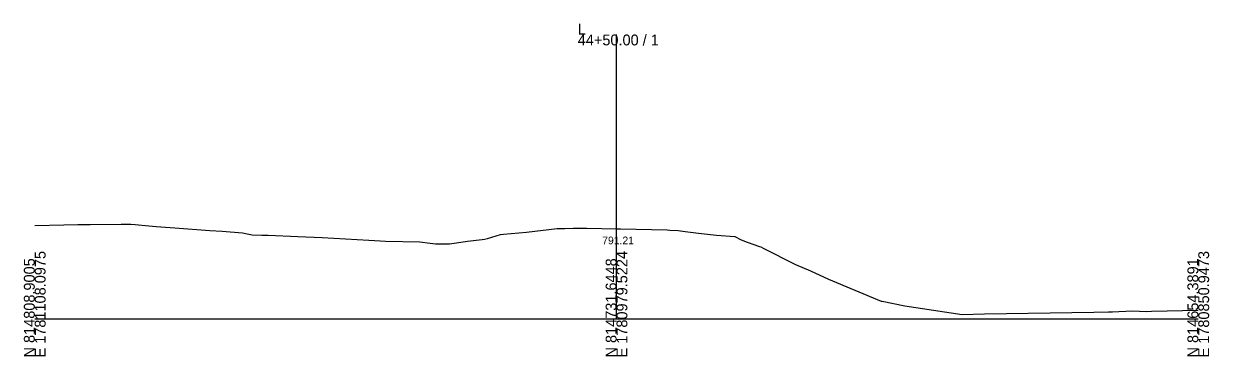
# Model space of a CAD drawing. Extents: x -26 to 7903, y -10 to 9573.
# Drawn here: x 997.2 to 1302.8, y 5490.3 to 5576.1 of the extents above; entities that cross this region are included whole.
import ezdxf

# ---------------------------------------------------------------- set-up
doc = ezdxf.new("R2010")
doc.units = 0
for name, color, linetype in [('Exist Cross Section Cell', 7, 'Continuous'), ('Exist XS Center Line Elevation Label', 7, 'Continuous'), ('Exist XS Ground Line', 7, 'Continuous')]:
    doc.layers.add(name, color=color, linetype=linetype)

msp = doc.modelspace()

# ---------------------------------------------------------------- linework, layer by layer
at = {"layer": 'Exist Cross Section Cell'}
for p, q in [((1150, 5500), (1150, 5573.35)), ((1000, 5500), (1150, 5500)), ((1150, 5500), (1300, 5500))]:
    msp.add_line(p, q, dxfattribs=at)
at = {"layer": 'Exist XS Ground Line'}
for p, q in [((1000, 5524.07), (1007.47, 5524.23)), ((1007.47, 5524.23), (1011.1, 5524.31)), ((1011.1, 5524.31), (1014.31, 5524.34)), ((1014.31, 5524.34), (1022.25, 5524.45)), ((1022.25, 5524.45), (1024.76, 5524.38)), ((1024.76, 5524.38), (1025.88, 5524.34)), ((1025.88, 5524.34), (1029.41, 5523.99)), ((1029.41, 5523.99), (1031.28, 5523.79)), ((1031.28, 5523.79), (1036.14, 5523.45)), ((1036.14, 5523.45), (1045.18, 5522.79)), ((1045.18, 5522.79), (1048.3, 5522.57)), ((1048.3, 5522.57), (1053.55, 5522.17)), ((1053.55, 5522.17), (1054.81, 5521.9)), ((1054.81, 5521.9), (1056.05, 5521.64)), ((1056.05, 5521.64), (1058.55, 5521.61)), ((1058.55, 5521.61), (1060.15, 5521.56)), ((1060.15, 5521.56), (1067.85, 5521.2)), ((1067.85, 5521.2), (1074.09, 5520.97)), ((1074.09, 5520.97), (1086.1, 5520.26)), ((1115.94, 5520.56), (1116.74, 5520.73)), ((1116.74, 5520.73), (1120.08, 5521.71)), ((1120.08, 5521.71), (1120.9, 5521.8)), ((1120.9, 5521.8), (1126.79, 5522.36)), ((1126.79, 5522.36), (1134.7, 5523.26)), ((1134.7, 5523.26), (1136.64, 5523.33)), ((1136.64, 5523.33), (1138.85, 5523.4)), ((1138.85, 5523.4), (1142.32, 5523.34)), ((1142.32, 5523.34), (1150, 5523.21)), ((1150, 5523.21), (1150.66, 5523.2)), ((1150.66, 5523.2), (1151, 5523.19)), ((1151, 5523.19), (1163.04, 5522.93)), ((1163.04, 5522.93), (1163.77, 5522.89)), ((1163.77, 5522.89), (1165.91, 5522.79)), ((1165.91, 5522.79), (1167.74, 5522.56)), ((1167.74, 5522.56), (1171.15, 5522.07)), ((1171.15, 5522.07), (1175.79, 5521.59)), ((1175.79, 5521.59), (1180.49, 5521.22)), ((1180.49, 5521.22), (1182.17, 5520.38)), ((1086.1, 5520.26), (1089.09, 5520.07)), ((1089.09, 5520.07), (1090.48, 5520.06)), ((1090.48, 5520.06), (1099.27, 5519.84)), ((1099.27, 5519.84), (1101.97, 5519.47)), ((1101.97, 5519.47), (1103.29, 5519.31)), ((1103.29, 5519.31), (1103.92, 5519.35)), ((1103.92, 5519.35), (1106.94, 5519.37)), ((1106.94, 5519.37), (1111.06, 5519.96)), ((1111.06, 5519.96), (1111.55, 5520.04)), ((1111.55, 5520.04), (1115.37, 5520.49)), ((1115.37, 5520.49), (1115.94, 5520.56)), ((1182.17, 5520.38), (1183.69, 5519.76)), ((1183.69, 5519.76), (1186.86, 5518.65)), ((1186.86, 5518.65), (1187.2, 5518.52)), ((1187.2, 5518.52), (1187.78, 5518.21)), ((1187.78, 5518.21), (1196.15, 5513.96)), ((1196.15, 5513.96), (1200.04, 5512.39)), ((1200.04, 5512.39), (1204.7, 5510.24)), ((1204.7, 5510.24), (1218.21, 5504.5)), ((1218.21, 5504.5), (1218.53, 5504.5)), ((1218.53, 5504.5), (1224.3, 5503.31)), ((1224.3, 5503.31), (1239.1, 5501.12)), ((1239.1, 5501.12), (1244.91, 5501.29)), ((1244.91, 5501.29), (1273.07, 5501.73)), ((1273.07, 5501.73), (1276.87, 5501.81)), ((1276.87, 5501.81), (1277.87, 5501.81)), ((1277.87, 5501.81), (1279.53, 5501.85)), ((1279.53, 5501.85), (1283.1, 5502.07)), ((1283.1, 5502.07), (1286.55, 5501.91)), ((1286.55, 5501.91), (1287.98, 5501.94)), ((1287.98, 5501.94), (1300, 5502.19))]:
    msp.add_line(p, q, dxfattribs=at)

# ---------------------------------------------------------------- texts
at = {"layer": 'Exist Cross Section Cell'}
for s, p in [('L', (1140, 5573.35)), ('44+50.00 / 1', (1140, 5570.55))]:
    msp.add_text(s, height=2.8, dxfattribs=at).set_placement(p)
for s, p in [('N 814808.9005', (1000, 5490)), ('E 1781108.0975', (1002.8, 5490)), ('N 814731.6448', (1150, 5490)), ('E 1780979.5224', (1152.8, 5490)), ('N 814654.3891', (1300, 5490)), ('E 1780850.9473', (1302.8, 5490))]:
    msp.add_text(s, height=2.8, rotation=90, dxfattribs=at).set_placement(p)
at = {"layer": 'Exist XS Center Line Elevation Label'}
msp.add_text('791.21', height=2, dxfattribs=at).set_placement((1146.32, 5519.21))

doc.saveas('drawing.dxf')
